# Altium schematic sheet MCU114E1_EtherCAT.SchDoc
size 431 x 279 mm; Date: Not shown in title block; ApprovedBy: Not shown in title block; CheckedBy: Not shown in title block; Author: Not shown in title block; CompanyName: Not shown in title block; Engineer: Not shown in title block; Organization: Not shown in title block; Address1: Not shown in title block; Address2: Not shown in title block; Address3: Not shown in title block; Address4: Not shown in title block; DocumentNumber: 6; Revision: Use project parameter SCH_Rev; SheetNumber: 6; SheetTotal: 11; PageSetup: Record=PageOptions¦CenterHorizontal=True¦CenterVertical=True¦PrintScale=1.00¦XCorrection=1.00¦YCorrection=1.00¦PrintKind=0¦BorderSize=5000000¦LeftOffset=0¦BottomOffset=0¦Orientation=2¦PaperLength=1000¦PaperWidth=1000¦Scale=100¦PaperSource=15¦PrintQuality=600¦MediaType=1¦DitherType=10¦PaperKind=Letter¦PrintScaleMode=1
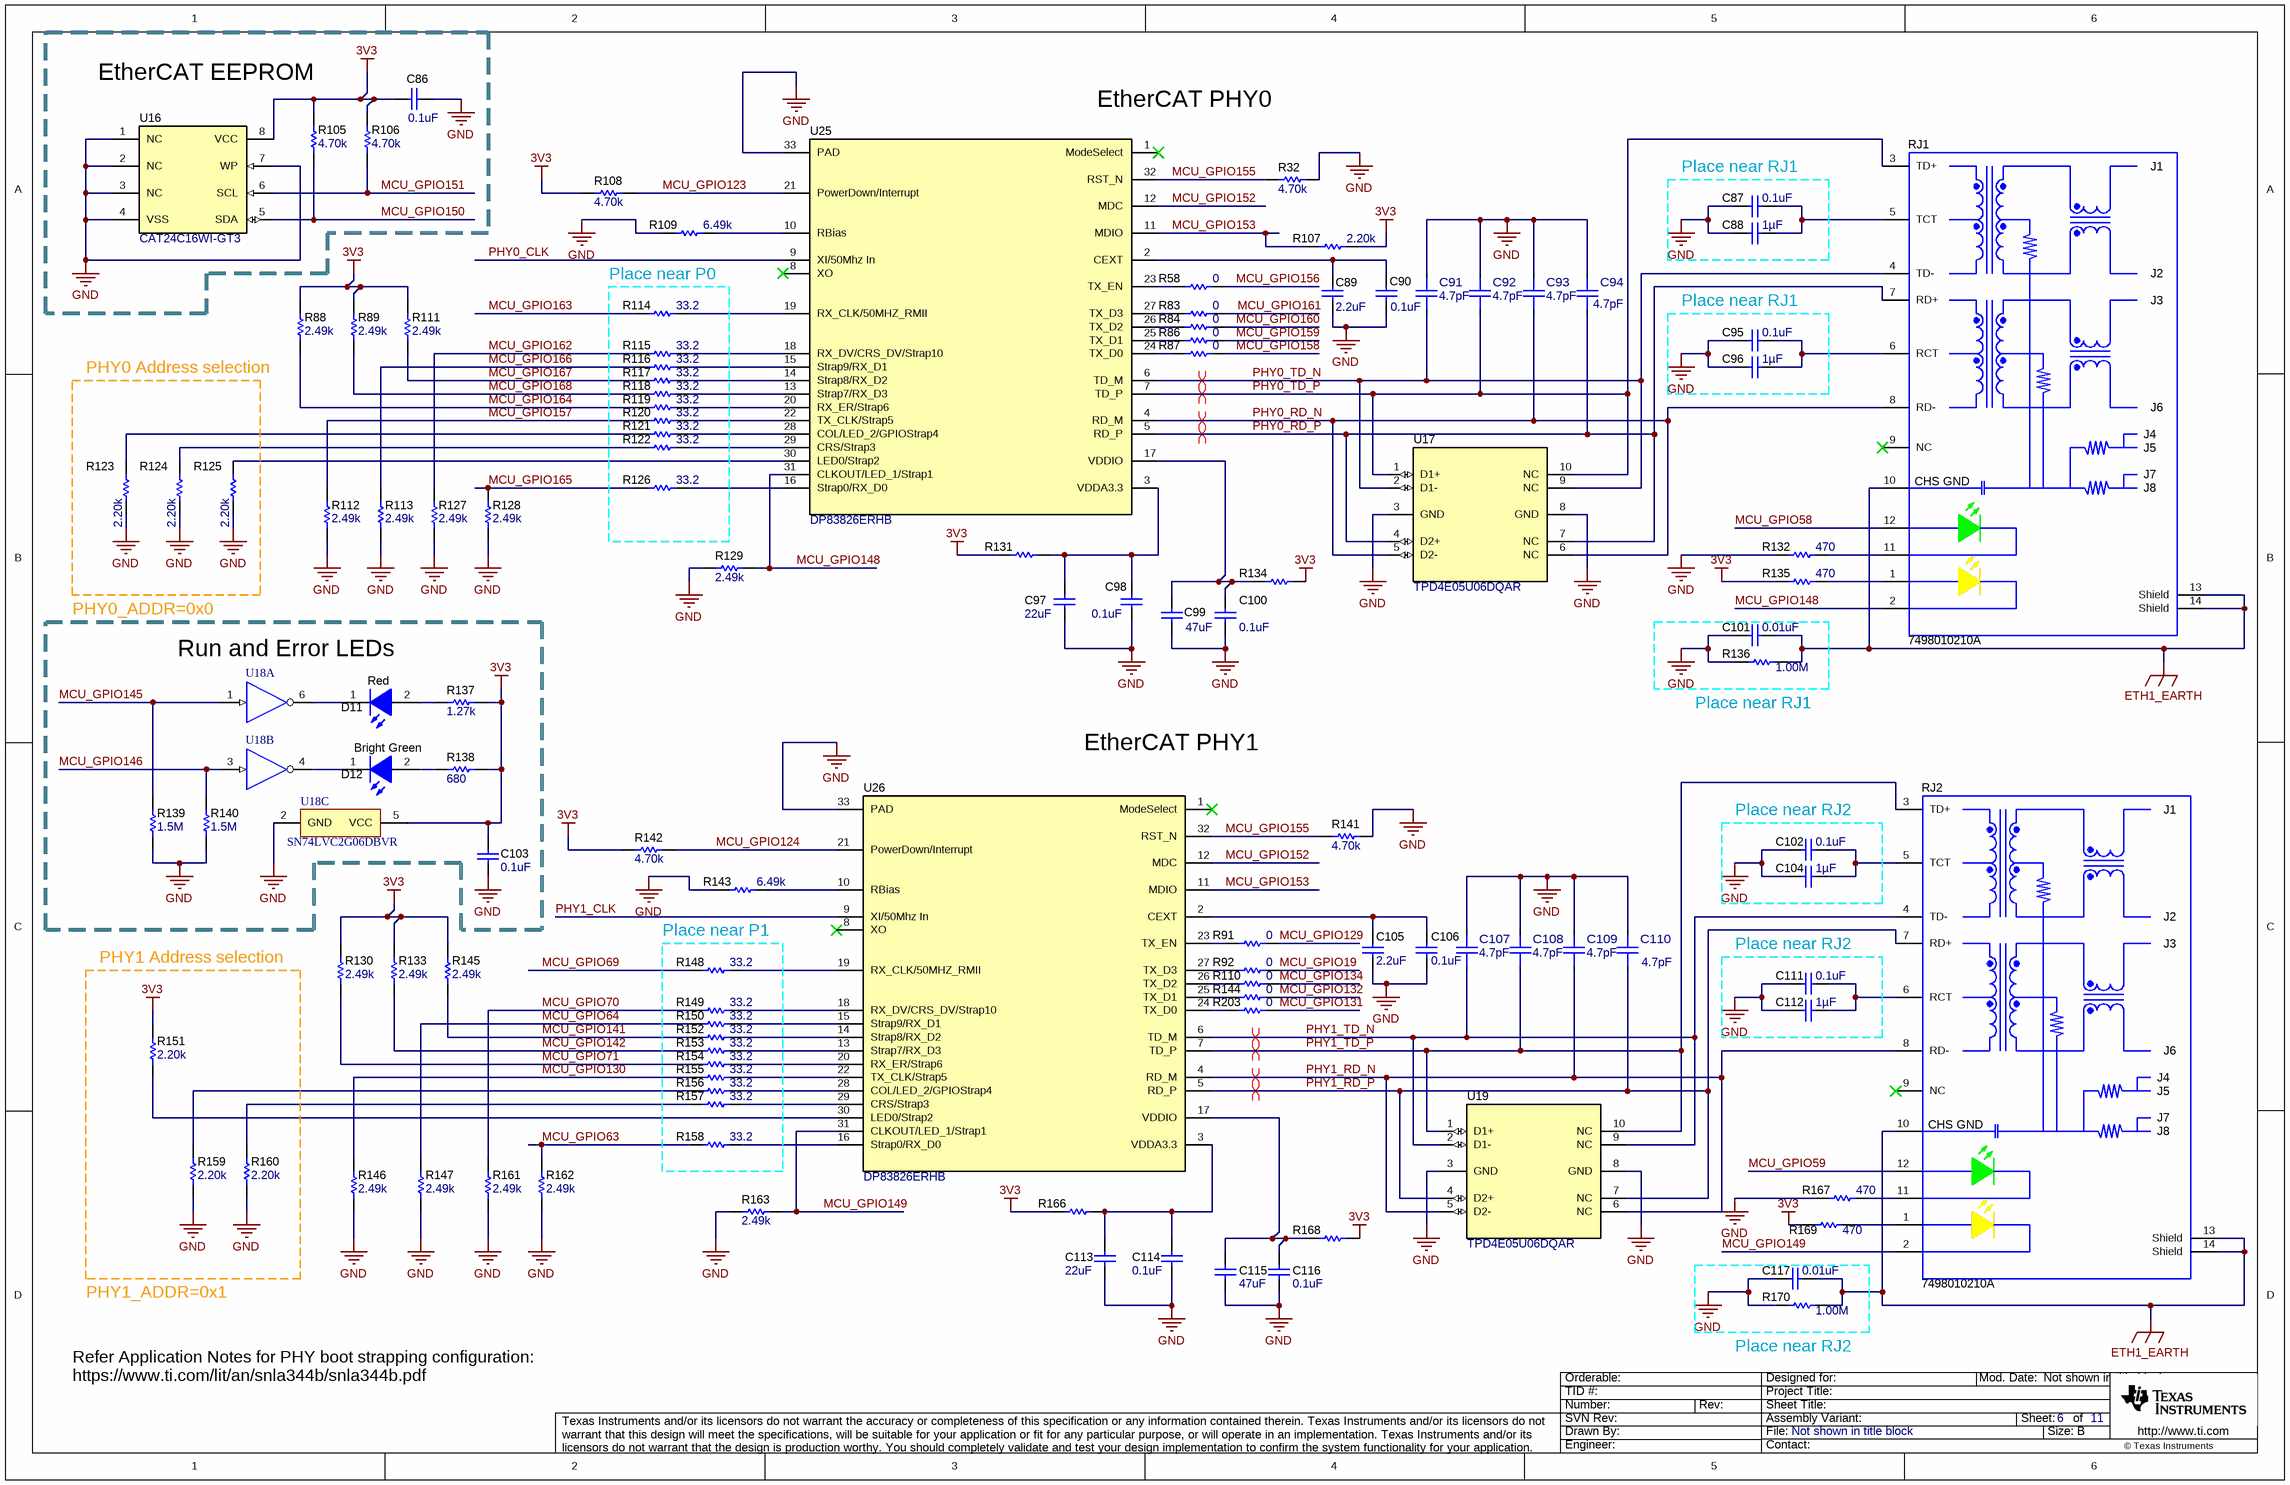
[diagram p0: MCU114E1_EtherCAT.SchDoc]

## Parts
C86  ValueDisplayed: 0.1uF  [0402]  (hidden comment: 885012205037)
C87  ValueDisplayed: 0.1uF  [0402]  (hidden comment: CGA2B3X7R1H104K050BB)
C88  ValueDisplayed: 1µF  [0402]  (hidden comment: GRM155R61E105KE11D)
C89  ValueDisplayed: 2.2uF  [0402_065]  (hidden comment: C1005X5R1V225K050BC)
C90  ValueDisplayed: 0.1uF  [0402]  (hidden comment: 885012205037)
C91  ValueDisplayed: 4.7pF  [FP-885012005053_0402-MFG]  (hidden comment: 885012005053)
C92  ValueDisplayed: 4.7pF  [FP-885012005053_0402-MFG]  (hidden comment: 885012005053)
C93  ValueDisplayed: 4.7pF  [FP-885012005053_0402-MFG]  (hidden comment: 885012005053)
C94  ValueDisplayed: 4.7pF  [FP-885012005053_0402-MFG]  (hidden comment: 885012005053)
C95  ValueDisplayed: 0.1uF  [0402]  (hidden comment: CGA2B3X7R1H104K050BB)
C96  ValueDisplayed: 1µF  [0402]  (hidden comment: GRM155R61E105KE11D)
C97  ValueDisplayed: 22uF  [0603]  (hidden comment: GRM188R61A226ME15D)
C98  ValueDisplayed: 0.1uF  [0402]  (hidden comment: 885012205037)
C99  ValueDisplayed: 47uF  [0603]  (hidden comment: GRM188R60J476ME15D)
C100  ValueDisplayed: 0.1uF  [0402]  (hidden comment: 885012205037)
C101  ValueDisplayed: 0.01uF  [0402]  (hidden comment: GRM155R71H103KA88D)
C102  ValueDisplayed: 0.1uF  [0402]  (hidden comment: CGA2B3X7R1H104K050BB)
C103  ValueDisplayed: 0.1uF  [0402]  (hidden comment: 885012205037)
C104  ValueDisplayed: 1µF  [0402]  (hidden comment: GRM155R61E105KE11D)
C105  ValueDisplayed: 2.2uF  [0402_065]  (hidden comment: C1005X5R1V225K050BC)
C106  ValueDisplayed: 0.1uF  [0402]  (hidden comment: 885012205037)
C107  ValueDisplayed: 4.7pF  [FP-885012005053_0402-MFG]  (hidden comment: 885012005053)
C108  ValueDisplayed: 4.7pF  [FP-885012005053_0402-MFG]  (hidden comment: 885012005053)
C109  ValueDisplayed: 4.7pF  [FP-885012005053_0402-MFG]  (hidden comment: 885012005053)
C110  ValueDisplayed: 4.7pF  [FP-885012005053_0402-MFG]  (hidden comment: 885012005053)
C111  ValueDisplayed: 0.1uF  [0402]  (hidden comment: CGA2B3X7R1H104K050BB)
C112  ValueDisplayed: 1µF  [0402]  (hidden comment: GRM155R61E105KE11D)
C113  ValueDisplayed: 22uF  [0603]  (hidden comment: GRM188R61A226ME15D)
C114  ValueDisplayed: 0.1uF  [0402]  (hidden comment: 885012205037)
C115  ValueDisplayed: 47uF  [0603]  (hidden comment: GRM188R60J476ME15D)
C116  ValueDisplayed: 0.1uF  [0402]  (hidden comment: 885012205037)
C117  ValueDisplayed: 0.01uF  [0402]  (hidden comment: GRM155R71H103KA88D)
D11  value Red  [WL-SMCW_RED_0805]  (hidden comment: 150080SS75000)
D12  value Bright Green  [WL-SMCW_Green_0805]  (hidden comment: 150080VS75000)
R32  ValueDisplayed: 4.70k  [0402]  (hidden comment: CRG0402F4K7)
R58  ValueDisplayed: 0  [0402]  (hidden comment: CRCW04020000Z0EDHP)
R83  ValueDisplayed: 0  [0402]  (hidden comment: CRCW04020000Z0EDHP)
R84  ValueDisplayed: 0  [0402]  (hidden comment: CRCW04020000Z0EDHP)
R86  ValueDisplayed: 0  [0402]  (hidden comment: CRCW04020000Z0EDHP)
R87  ValueDisplayed: 0  [0402]  (hidden comment: CRCW04020000Z0EDHP)
R88  ValueDisplayed: 2.49k  [0402]  (hidden comment: CRCW04022K49FKED)
R89  ValueDisplayed: 2.49k  [0402]  (hidden comment: CRCW04022K49FKED)
R91  ValueDisplayed: 0  [0402]  (hidden comment: CRCW04020000Z0EDHP)
R92  ValueDisplayed: 0  [0402]  (hidden comment: CRCW04020000Z0EDHP)
R105  ValueDisplayed: 4.70k  [0402]  (hidden comment: CRG0402F4K7)
R106  ValueDisplayed: 4.70k  [0402]  (hidden comment: CRG0402F4K7)
R107  ValueDisplayed: 2.20k  [0402]  (hidden comment: CRCW04022K20FKED)
R108  ValueDisplayed: 4.70k  [0402]  (hidden comment: CRG0402F4K7)
R109  ValueDisplayed: 6.49k  [0402]  (hidden comment: CRCW04026K49FKED)
R110  ValueDisplayed: 0  [0402]  (hidden comment: CRCW04020000Z0EDHP)
R111  ValueDisplayed: 2.49k  [0402]  (hidden comment: CRCW04022K49FKED)
R112  ValueDisplayed: 2.49k  [0402]  (hidden comment: CRCW04022K49FKED)
R113  ValueDisplayed: 2.49k  [0402]  (hidden comment: CRCW04022K49FKED)
R114  ValueDisplayed: 33.2  [0402]  (hidden comment: CRCW040233R2FKED)
R115  ValueDisplayed: 33.2  [0402]  (hidden comment: CRCW040233R2FKED)
R116  ValueDisplayed: 33.2  [0402]  (hidden comment: CRCW040233R2FKED)
R117  ValueDisplayed: 33.2  [0402]  (hidden comment: CRCW040233R2FKED)
R118  ValueDisplayed: 33.2  [0402]  (hidden comment: CRCW040233R2FKED)
R119  ValueDisplayed: 33.2  [0402]  (hidden comment: CRCW040233R2FKED)
R120  ValueDisplayed: 33.2  [0402]  (hidden comment: CRCW040233R2FKED)
R121  ValueDisplayed: 33.2  [0402]  (hidden comment: CRCW040233R2FKED)
R122  ValueDisplayed: 33.2  [0402]  (hidden comment: CRCW040233R2FKED)
R123  ValueDisplayed: 2.20k  [0402]  (hidden comment: CRCW04022K20FKED)
R124  ValueDisplayed: 2.20k  [0402]  (hidden comment: CRCW04022K20FKED)
R125  ValueDisplayed: 2.20k  [0402]  (hidden comment: CRCW04022K20FKED)
R126  ValueDisplayed: 33.2  [0402]  (hidden comment: CRCW040233R2FKED)
R127  ValueDisplayed: 2.49k  [0402]  (hidden comment: CRCW04022K49FKED)
R128  ValueDisplayed: 2.49k  [0402]  (hidden comment: CRCW04022K49FKED)
R129  ValueDisplayed: 2.49k  [0402]  (hidden comment: CRCW04022K49FKED)
R130  ValueDisplayed: 2.49k  [0402]  (hidden comment: CRCW04022K49FKED)
R131  RMCF0402ZT0R00  [FP-RMCF0402ZT0R00_0402 (1005 metric)-0]  (value not drawn)
R132  ValueDisplayed: 470  [0603]  (hidden comment: CRCW0603470RJNEA)
R133  ValueDisplayed: 2.49k  [0402]  (hidden comment: CRCW04022K49FKED)
R134  RMCF0402ZT0R00  [FP-RMCF0402ZT0R00_0402 (1005 metric)-0]  (value not drawn)
R135  ValueDisplayed: 470  [0603]  (hidden comment: CRCW0603470RJNEA)
R136  ValueDisplayed: 1.00M  [0402]  (hidden comment: RMCF0402FT1M00)
R137  ValueDisplayed: 1.27k  [0402]  (hidden comment: CRCW04021K27FKED)
R138  ValueDisplayed: 680  [0402]  (hidden comment: CRCW0402680RJNED)
R139  ValueDisplayed: 1.5M  [0402]  (hidden comment: CRCW04021M50JNED)
R140  ValueDisplayed: 1.5M  [0402]  (hidden comment: CRCW04021M50JNED)
R141  ValueDisplayed: 4.70k  [0402]  (hidden comment: CRG0402F4K7)
R142  ValueDisplayed: 4.70k  [0402]  (hidden comment: CRG0402F4K7)
R143  ValueDisplayed: 6.49k  [0402]  (hidden comment: CRCW04026K49FKED)
R144  ValueDisplayed: 0  [0402]  (hidden comment: CRCW04020000Z0EDHP)
R145  ValueDisplayed: 2.49k  [0402]  (hidden comment: CRCW04022K49FKED)
R146  ValueDisplayed: 2.49k  [0402]  (hidden comment: CRCW04022K49FKED)
R147  ValueDisplayed: 2.49k  [0402]  (hidden comment: CRCW04022K49FKED)
R148  ValueDisplayed: 33.2  [0402]  (hidden comment: CRCW040233R2FKED)
R149  ValueDisplayed: 33.2  [0402]  (hidden comment: CRCW040233R2FKED)
R150  ValueDisplayed: 33.2  [0402]  (hidden comment: CRCW040233R2FKED)
R151  ValueDisplayed: 2.20k  [0402]  (hidden comment: CRCW04022K20FKED)
R152  ValueDisplayed: 33.2  [0402]  (hidden comment: CRCW040233R2FKED)
R153  ValueDisplayed: 33.2  [0402]  (hidden comment: CRCW040233R2FKED)
R154  ValueDisplayed: 33.2  [0402]  (hidden comment: CRCW040233R2FKED)
R155  ValueDisplayed: 33.2  [0402]  (hidden comment: CRCW040233R2FKED)
R156  ValueDisplayed: 33.2  [0402]  (hidden comment: CRCW040233R2FKED)
R157  ValueDisplayed: 33.2  [0402]  (hidden comment: CRCW040233R2FKED)
R158  ValueDisplayed: 33.2  [0402]  (hidden comment: CRCW040233R2FKED)
R159  ValueDisplayed: 2.20k  [0402]  (hidden comment: CRCW04022K20FKED)
R160  ValueDisplayed: 2.20k  [0402]  (hidden comment: CRCW04022K20FKED)
R161  ValueDisplayed: 2.49k  [0402]  (hidden comment: CRCW04022K49FKED)
R162  ValueDisplayed: 2.49k  [0402]  (hidden comment: CRCW04022K49FKED)
R163  ValueDisplayed: 2.49k  [0402]  (hidden comment: CRCW04022K49FKED)
R166  RMCF0402ZT0R00  [FP-RMCF0402ZT0R00_0402 (1005 metric)-0]  (value not drawn)
R167  ValueDisplayed: 470  [0603]  (hidden comment: CRCW0603470RJNEA)
R168  RMCF0402ZT0R00  [FP-RMCF0402ZT0R00_0402 (1005 metric)-0]  (value not drawn)
R169  ValueDisplayed: 470  [0603]  (hidden comment: CRCW0603470RJNEA)
R170  ValueDisplayed: 1.00M  [0402]  (hidden comment: RMCF0402FT1M00)
R203  ValueDisplayed: 0  [0402]  (hidden comment: CRCW04020000Z0EDHP)
RJ1  7498010210A  [Wurth_7498010210A]
RJ2  7498010210A  [Wurth_7498010210A]
U16  CAT24C16WI-GT3  [SOIC-8]
U17  TPD4E05U06DQAR  [DQA0010A]
U18  SN74LVC2G06DBVR  [DBV0006A_N]  (parts A,B,C of 3)
U19  TPD4E05U06DQAR  [DQA0010A]
U25  DP83826ERHB  [RHB0032M]
U26  DP83826ERHB  [RHB0032M]

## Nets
3V3: C86.2 C103.1 R88.2 R89.2 R105.2 R106.2 R107.2 R108.1 R111.2 R130.2 R131.1 R133.2 R134.2 R135.1 R137.2 R138.1 R142.1 R145.2 R151.2 R166.1 R168.2 R169.1 U16.8(VCC) U18.5(VCC)
ETH1_EARTH: C101.2 C117.2 R136.2 R170.2 RJ1.10(CHS_GND) RJ1.13(Shield) RJ1.14(Shield) RJ2.10(CHS_GND) RJ2.13(Shield) RJ2.14(Shield)
GND: C86.1 C87.1 C88.1 C89.2 C90.2 C91.2 C92.2 C93.2 C94.2 C95.1 C96.1 C97.2 C98.2 C99.2 C100.2 C101.1 C102.1 C103.2 C104.1 C105.2 C106.2 C107.2 C108.2 C109.2 C110.2 C111.1 C112.1 C113.2 C114.1 C115.2 C116.1 C117.1 R32.2 R109.1 R112.1 R113.1 R123.1 R124.1 R125.1 R127.1 R128.1 R129.1 R132.1 R136.1 R139.2 R140.2 R141.2 R143.1 R146.1 R147.1 R159.1 R160.1 R161.1 R162.1 R163.2 R167.1 R170.1 U16.1(NC) U16.2(NC) U16.3(NC) U16.4(VSS) U16.7(WP) U17.3(GND) U17.8(GND) U18.2(GND) U19.3(GND) U19.8(GND) U25.33(PAD) U26.33(PAD)
MCU_GPIO19: R92.2
MCU_GPIO58: RJ1.12(LEFT_LED_ANODE)
MCU_GPIO59: RJ2.12(LEFT_LED_ANODE)
MCU_GPIO63: R158.1 R162.2
MCU_GPIO64: R147.2 R150.1
MCU_GPIO69: R148.1
MCU_GPIO70: R149.1 R161.2
MCU_GPIO71: R130.1 R154.1
MCU_GPIO123: R108.2 U25.21(PowerDown/Interrupt)
MCU_GPIO124: R142.2 U26.21(PowerDown/Interrupt)
MCU_GPIO129: R91.2
MCU_GPIO130: R146.2 R155.1
MCU_GPIO131: R203.2
MCU_GPIO132: R144.2
MCU_GPIO134: R110.2
MCU_GPIO141: R145.1 R152.1
MCU_GPIO142: R133.1 R153.1
MCU_GPIO145: R139.1 U18.1(1A)
MCU_GPIO146: R140.1 U18.3(2A)
MCU_GPIO148: R129.2 RJ1.2(RIGHT_LED_CATHODE) U25.31(CLKOUT/LED_1/Strap1)
MCU_GPIO149: R163.1 RJ2.2(RIGHT_LED_CATHODE) U26.31(CLKOUT/LED_1/Strap1)
MCU_GPIO150: R105.1 U16.5(SDA)
MCU_GPIO151: R106.1 U16.6(SCL)
MCU_GPIO152: U25.12(MDC) U26.12(MDC)
MCU_GPIO153: R107.1 U25.11(MDIO) U26.11(MDIO)
MCU_GPIO155: R32.1 R141.1 U25.32(RST_N) U26.32(RST_N)
MCU_GPIO156: R58.2
MCU_GPIO157: R112.2 R120.1
MCU_GPIO158: R87.2
MCU_GPIO159: R86.2
MCU_GPIO160: R84.2
MCU_GPIO161: R83.2
MCU_GPIO162: R115.1 R127.2
MCU_GPIO163: R114.1
MCU_GPIO164: R88.1 R119.1
MCU_GPIO165: R126.1 R128.2
MCU_GPIO166: R113.2 R116.1
MCU_GPIO167: R111.1 R117.1
MCU_GPIO168: R89.1 R118.1
PHY0_CLK: U25.9(XI/50Mhz_In)
PHY0_RD_N: C93.1 RJ1.8(RD-) U17.5(D2-) U17.6(NC) U25.4(RD_M)
PHY0_RD_P: C94.1 RJ1.7(RD+) U17.4(D2+) U17.7(NC) U25.5(RD_P)
PHY0_TD_N: C91.1 RJ1.4(TD-) U17.2(D1-) U17.9(NC) U25.6(TD_M)
PHY0_TD_P: C92.1 RJ1.3(TD+) U17.1(D1+) U17.10(NC) U25.7(TD_P)
PHY1_CLK: U26.9(XI/50Mhz_In)
PHY1_RD_N: C109.1 RJ2.8(RD-) U19.5(D2-) U19.6(NC) U26.4(RD_M)
PHY1_RD_P: C110.1 RJ2.7(RD+) U19.4(D2+) U19.7(NC) U26.5(RD_P)
PHY1_TD_N: C107.1 RJ2.4(TD-) U19.2(D1-) U19.9(NC) U26.6(TD_M)
PHY1_TD_P: C108.1 RJ2.3(TD+) U19.1(D1+) U19.10(NC) U26.7(TD_P)
NetC87_2: C87.2 C88.2 RJ1.5(TCT)
NetC89_1: C89.1 C90.1 U25.2(CEXT)
NetC95_2: C95.2 C96.2 RJ1.6(RCT)
NetC97_1: C97.1 C98.1 R131.2 U25.3(VDDA3.3)
NetC99_1: C99.1 C100.1 R134.1 U25.17(VDDIO)
NetC102_2: C102.2 C104.2 RJ2.5(TCT)
NetC105_1: C105.1 C106.1 U26.2(CEXT)
NetC111_2: C111.2 C112.2 RJ2.6(RCT)
NetC113_1: C113.1 C114.2 R166.2 U26.3(VDDA3.3)
NetC115_1: C115.1 C116.2 R168.1 U26.17(VDDIO)
NetD11_1: D11.1(K) U18.6(1Y)
NetD11_2: D11.2(A) R137.1
NetD12_1: D12.1(K) U18.4(2Y)
NetD12_2: D12.2(A) R138.2
NetR58_1: R58.1 U25.23(TX_EN)
NetR83_1: R83.1 U25.27(TX_D3)
NetR84_1: R84.1 U25.26(TX_D2)
NetR86_1: R86.1 U25.25(TX_D1)
NetR87_1: R87.1 U25.24(TX_D0)
NetR91_1: R91.1 U26.23(TX_EN)
NetR92_1: R92.1 U26.27(TX_D3)
NetR109_2: R109.2 U25.10(RBias)
NetR110_1: R110.1 U26.26(TX_D2)
NetR114_2: R114.2 U25.19(RX_CLK/50MHZ_RMII)
NetR115_2: R115.2 U25.18(RX_DV/CRS_DV/Strap10)
NetR116_2: R116.2 U25.15(Strap9/RX_D1)
NetR117_2: R117.2 U25.14(Strap8/RX_D2)
NetR118_2: R118.2 U25.13(Strap7/RX_D3)
NetR119_2: R119.2 U25.20(RX_ER/Strap6)
NetR120_2: R120.2 U25.22(TX_CLK/Strap5)
NetR121_1: R121.1 R123.2
NetR121_2: R121.2 U25.28(COL/LED_2/GPIOStrap4)
NetR122_1: R122.1 R124.2
NetR122_2: R122.2 U25.29(CRS/Strap3)
NetR125_2: R125.2 U25.30(LED0/Strap2)
NetR126_2: R126.2 U25.16(Strap0/RX_D0)
NetR132_2: R132.2 RJ1.11(LEFT_LED_CATHODE)
NetR135_2: R135.2 RJ1.1(RIGHT_LED_ANODE)
NetR143_2: R143.2 U26.10(RBias)
NetR144_1: R144.1 U26.25(TX_D1)
NetR148_2: R148.2 U26.19(RX_CLK/50MHZ_RMII)
NetR149_2: R149.2 U26.18(RX_DV/CRS_DV/Strap10)
NetR150_2: R150.2 U26.15(Strap9/RX_D1)
NetR151_1: R151.1 U26.30(LED0/Strap2)
NetR152_2: R152.2 U26.14(Strap8/RX_D2)
NetR153_2: R153.2 U26.13(Strap7/RX_D3)
NetR154_2: R154.2 U26.20(RX_ER/Strap6)
NetR155_2: R155.2 U26.22(TX_CLK/Strap5)
NetR156_1: R156.1 R159.2
NetR156_2: R156.2 U26.28(COL/LED_2/GPIOStrap4)
NetR157_1: R157.1 R160.2
NetR157_2: R157.2 U26.29(CRS/Strap3)
NetR158_2: R158.2 U26.16(Strap0/RX_D0)
NetR167_2: R167.2 RJ2.11(LEFT_LED_CATHODE)
NetR169_2: R169.2 RJ2.1(RIGHT_LED_ANODE)
NetR203_1: R203.1 U26.24(TX_D0)

Not connected (* = marked no-connect by the designer): RJ1 9(NC)*; RJ2 9(NC)*; U25 1(ModeSelect)* 8(XO)*; U26 1(ModeSelect)* 8(XO)*

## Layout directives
differential pair: PHY0_RD_N, PHY0_RD_P, PHY0_TD_N, PHY0_TD_P, PHY1_RD_N, PHY1_RD_P, PHY1_TD_N, PHY1_TD_P

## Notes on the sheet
- EtherCAT EEPROM
- (near U25) EtherCAT PHY0
- (near C87) Place near RJ1
- Place near P0
- (near C95) Place near RJ1
- (near R88) PHY0 Address selection
- PHY0_ADDR=0x0
- Run and Error LEDs
- (near R136) Place near RJ1
- EtherCAT PHY1
- (near C102) Place near RJ2
- PHY1 Address selection
- Place near P1
- (near C111) Place near RJ2
- PHY1_ADDR=0x1
- (near R170) Place near RJ2
- Refer Application Notes for PHY boot strapping configuration: https://www.ti.com/lit/an/snla344b/snla344b.pdf

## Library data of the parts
C86 C90 C98 C100 C103 C106 C114 C116 = CMP-0006228-2: CAP, CERM, 0.1 uF, 16 V, +/- 10%, X7R, 0402; Manufacturer: Wurth Elektronik; TaMin_C: -55°C; Polarized: N; SizeAreaWB_mm2: 3; Value1: Unknown; U/M: EA; Value: 0.1uF; TaMax_C: 125°C; SizeZ_mm: 0.6; SizeX_mm: 1; SizeY_mm: 0.5; Value2: 16V; Cap_F: 100nF; AEC Category: Q200
C87 C95 C102 C111 = CMP-0006325-2: CAP, CERM, 0.1 uF, 50 V, +/- 10%, X7R, AEC-Q200 Grade 1, 0402; Manufacturer: TDK; TaMin_C: -55°C; ESR_ohm: 39.064m; Polarized: N; SizeAreaWB_mm2: 3; Value1: 0.039064 ohm; U/M: EA; Value: 0.1uF; TaMax_C: 125°C; SizeZ_mm: 0.6; SizeX_mm: 1; SizeY_mm: 0.5; Value2: 50V; AEC Qualified: Y; Cap_F: 100nF; IRMS_A: 814.669mA; AEC Category: Q200
C88 C96 C104 C112 = CMP-0086061-1: CAP, CERM, 1 µF, 25 V,+/- 10%, X5R, 0402; Manufacturer: MuRata; SizeY_mm: 0.5; TaMin_C: -55°C; VDC_V: 25V; Polarized: N; AEC Category: Q200; SizeX_mm: 1; SizeAreaWB_mm2: 3; SizeZ_mm: 0.6; Value: 1uF; TaMax_C: 85°C; U/M: EA
C89 C105 = CMP-0006283-2: CAP, CERM, 2.2 uF, 35 V, +/- 10%, X5R, 0402; Manufacturer: TDK; TaMin_C: -55°C; ESR_ohm: 5.925m; Polarized: N; SizeAreaWB_mm2: 3; Value1: 0.005925 ohm; U/M: EA; Value: 2.2uF; TaMax_C: 85°C; SizeZ_mm: 0.65; SizeX_mm: 1; SizeY_mm: 0.5; Value2: 35V; Cap_F: 2.2µF; IRMS_A: 2.0559A; AEC Category: Q200
C91-C94 C107-C110 = CMP-0096999-1: 4.7 pF ±0.5pF 50V Ceramic Capacitor C0G, NP0 0402 (1005 Metric); Manufacturer: Wurth Electronics; Value: 4.7pF; TempCo: 30ppm/°C; SizeZ_mm: 0.55mm; AEC Qualified: No
C97 C113 = CMP-0007324-5: CAP, CERM, 22 uF, 10 V, +/- 20%, X5R, 0603; Manufacturer: MuRata; TaMin_C: -55°C; Polarized: N; SizeAreaWB_mm2: 4.68; Value1: Unknown; U/M: EA; Value: 22uF; TaMax_C: 85°C; SizeZ_mm: 1; SizeX_mm: 1.6; SizeY_mm: 0.8; Value2: 10V; SizeArea_mm2: 1.28; Cap_F: 22µF; AEC Category: Q200
C99 C115 = CMP-0007313-5: CAP, CERM, 47 uF, 6.3 V, +/- 20%, X5R, 0603; Manufacturer: MuRata; TaMin_C: -55°C; Polarized: N; SizeAreaWB_mm2: 4.68; Value1: Unknown; U/M: EA; Value: 47uF; TaMax_C: 85°C; SizeZ_mm: 1; SizeX_mm: 1.6; SizeY_mm: 0.8; Value2: 6.3V; SizeArea_mm2: 1.28; Cap_F: 47µF; AEC Category: Q200
C101 C117 = CMP-0006674-2: CAP, CERM, 0.01 uF, 50 V, +/- 10%, X7R, 0402; Manufacturer: MuRata; TaMin_C: -55°C; Polarized: N; SizeAreaWB_mm2: 3; Value1: Unknown; U/M: EA; Value: 0.01uF; TaMax_C: 125°C; SizeZ_mm: 0.6; SizeX_mm: 1; SizeY_mm: 0.5; Value2: 50V; Cap_F: 10nF; AEC Category: Q200
D11 = CMP-0002951-3: LED, Red, SMD; Manufacturer: Wurth Elektronik; Type: AlInGaP; Vf_V: 1.9V; Io_A: 30mA; Vr_V: 5V; Ir_A: 25µA; Tjmax_C: 85°C; Power_TotalModule: 72mW; Value1: 0.072W; Angle: 140
D12 = CMP-0002960-2: LED, Bright Green, SMD; Manufacturer: Wurth Elektronik; Type: AlInGaP; Vf_V: 2V; Io_A: 20mA; Vr_V: 5V; Tjmax_C: 85°C; Power_TotalModule: 72mW; Value1: 0.072W; Angle: 140; U/M: EA
R32 R105 R106 R108 R141 R142 = CMP-0026631-1: RES, 4.70 k, 1%, 0.063 W, 0402; Manufacturer: TE Connectivity; Power_W: 63mW; TempCo: 100 ppm/C; Value_Code: 4k70; U/M: EA; Value: 4.70k; Res_ohm: 4.7k; SizeX_mm: 1; SizeY_mm: 0.5; SizeZ_mm: 0.6; Value2: 0.063W; AEC Qualified: N; AEC Category: Q200
R58 R83 R84 R86 R87 R91 R92 R110 R144 R203 = CMP-0081856-1: RES, 0, 0%, 0.2 W, AEC-Q200 Grade 0, 0402; Manufacturer: Vishay-Dale; SizeAreaWB_mm2: 3; SizeArea_mm2: 0.5; AEC Qualified: Y; AEC Category: Q200; Value: 0; SizeZ_mm: 0.6; Power_W: 200mW; VDC_V: 50V; Value2: 0.2W; SizeX_mm: 1
R88 R89 R111-R113 R127-R130 R133 R145-R147 R161-R163 = CMP-0026237-2: RES, 2.49 k, 1%, 0.063 W, AEC-Q200 Grade 0, 0402; Manufacturer: Vishay-Dale; Power_W: 63mW; TempCo: 100 ppm/C; Value_Code: 2k49; Value: 2.49k; EIA_Code: E96; SizeX_mm: 1; SizeY_mm: 0.5; SizeZ_mm: 0.6; Value2: 0.063W; AEC Qualified: Y; VDC_V: 50V; AEC Category: Q200; AEC Grade: 0
R107 R123-R125 R151 R159 R160 = CMP-0026231-2: RES, 2.20 k, 1%, 0.063 W, AEC-Q200 Grade 0, 0402; Manufacturer: Vishay-Dale; Power_W: 63mW; TempCo: 100 ppm/C; Value_Code: 2k20; Value: 2.20k; Res_ohm: 2.2k; SizeX_mm: 1; SizeY_mm: 0.5; SizeZ_mm: 0.6; Value2: 0.063W; AEC Qualified: Y; AEC Category: Q200; AEC Grade: 0
R109 R143 = CMP-0026515-2: RES, 6.49 k, 1%, 0.063 W, AEC-Q200 Grade 0, 0402; Manufacturer: Vishay-Dale; Power_W: 63mW; TempCo: 100 ppm/C; Value_Code: 6k49; Value: 6.49k; EIA_Code: E96; SizeX_mm: 1; SizeY_mm: 0.5; SizeZ_mm: 0.6; Value2: 0.063W; AEC Qualified: Y; VDC_V: 50V; AEC Category: Q200; AEC Grade: 0
R114-R122 R126 R148-R150 R152-R158 = CMP-0026299-2: RES, 33.2, 1%, 0.063 W, AEC-Q200 Grade 0, 0402; Manufacturer: Vishay-Dale; Power_W: 63mW; TempCo: 100 ppm/C; Value_Code: 33R2; Value: 33.2; EIA_Code: E96; SizeX_mm: 1; SizeY_mm: 0.5; SizeZ_mm: 0.6; Value2: 0.063W; AEC Qualified: Y; VDC_V: 50V; AEC Category: Q200; AEC Grade: 0
R131 R134 R166 R168 = CMP-0086542-2: RMCF/RMCP Series General Purpose Thick Film Standard Power and High Power Chip Resistor; Manufacturer: Stackpole
R132 R135 R167 R169 = CMP-0025813-4: RES, 470, 5%, 0.1 W, AEC-Q200 Grade 0, 0603; Manufacturer: Vishay-Dale; Power_W: 100mW; TempCo: 200 ppm/C; Value_Code: 470R; Value: 470; EIA_Code: E24; SizeX_mm: 1.6; SizeY_mm: 0.8; SizeZ_mm: 1; Value2: 0.1W; SizeArea_mm2: 1.28; AEC Qualified: Y; VDC_V: 75V; AEC Category: Q200; AEC Grade: 0
R136 R170 = CMP-0026757-1: RES, 1.00 M, 1%, 0.063 W, AEC-Q200 Grade 0, 0402; Manufacturer: Stackpole Electronics Inc; Power_W: 63mW; TempCo: 100 ppm/C; Value_Code: 1M00; U/M: EA; Value: 1.00Meg; EIA_Code: E96; Res_ohm: 1M; SizeX_mm: 1; SizeY_mm: 0.5; SizeZ_mm: 0.6; Value2: 0.063W; AEC Qualified: Y; VDC_V: 50V; AEC Grade: 0; AEC Category: Q200
R137 = CMP-0026081-3: RES, 1.27 k, 1%, 0.063 W, AEC-Q200 Grade 0, 0402; Manufacturer: Vishay-Dale; Power_W: 63mW; TempCo: 100 ppm/C; Value_Code: 1k27; Value: 1.27k; EIA_Code: E96; SizeX_mm: 1; SizeY_mm: 0.5; SizeZ_mm: 0.6; Value2: 0.063W; AEC Qualified: Y; VDC_V: 50V; AEC Category: Q200; AEC Grade: 0
R138 = CMP-0026962-3: RES, 680, 5%, 0.063 W, AEC-Q200 Grade 0, 0402; Manufacturer: Vishay-Dale; Value: 680; Value_Code: 680R; Power_W: 63mW; Value2: 0.063W; VDC_V: 50V; TempCo: 200 ppm/C; EIA_Code: E24; AEC Category: Q200; AEC Qualified: Y; AEC Grade: 0; SizeArea_mm2: 0.5; SizeX_mm: 1; SizeZ_mm: 0.6
R139 R140 = CMP-0026863-2: RES, 1.5 M, 5%, 0.063 W, AEC-Q200 Grade 0, 0402; Manufacturer: Vishay-Dale; Power_W: 63mW; TempCo: 200 ppm/C; Value_Code: 1M50; Value: 1.5Meg; EIA_Code: E24; SizeX_mm: 1; SizeY_mm: 0.5; SizeZ_mm: 0.6; Value2: 0.063W; AEC Qualified: Y; VDC_V: 50V; AEC Category: Q200; AEC Grade: 0
RJ1 RJ2 = CMP-0086350-1: Connector, RJ45, 1x1, Gold, R/A, SMT; Manufacturer: Wurth Elektronik; Row_Count: 1; Gender: Female
U16 = CMP-0082059-1: 16 Kb I2C EEPROM Serial, SOIC-8; Manufacturer: ON Semiconductor; SizeArea_mm2: 29.351; SizeAreaWB_mm2: 55.131; SizeY_mm: 4.9; SizeZ_mm: 1.75; SizeX_mm: 5.99
U17 U19 = CMP-0073613-3: 4-Channel Ultra-Low-Capacitance IEC ESD Protection Diode, DQA0010A (USON-10); Alternate Manufacturer: Texas Instruments; Green_Lifecycle: Active; SizeAreaWB_mm2: 7.0; Green_REACh: Passed; SizeZ_mm: 0.55; SizeX_mm: 1.0; SizeY_mm: 2.5; CompType: IC; AEC Category: Q200; AEC Qualified: N
U18 = CMP-0051777-2: Dual Inverter Buffer/Driver with Open-Drain Output, DBV0006A, LARGE T&R; Manufacturer: Texas Instruments; Schmitt Trigger: No; Logic: Inverting; F @ Nom Voltage(Max)(Mhz): 150; VCC(Max)(V): 5.5; Rating: Catalog; Sub-Family: Inverting Buffer/Driver; Technology Family: LVC; VCC(Min)(V): 1.65; Voltage(Nom)(V): 1.8,2.5,3.3,5; Output Drive (IOL/IOH)(Max)(mA): 32/-32; Output Type: CMOS; ICC @ Nom Voltage(Max)(mA): 0.01; Bits(#): 2; tpd @ Nom Voltage(Max)(ns): 8.2,4.4,3.9,3.4; Input Type: CMOS/TTL
U25 U26 = CMP-0860427-2: DP83826ERHB, RHB0032M (VQFN-32); Alternate Manufacturer: Texas Instruments; AEC Category: Q200; SizeArea_mm2: 25; SizeAreaWB_mm2: 49; AEC Qualified: N; CompType: IC; SizeY_mm: 5; SizeZ_mm: 1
